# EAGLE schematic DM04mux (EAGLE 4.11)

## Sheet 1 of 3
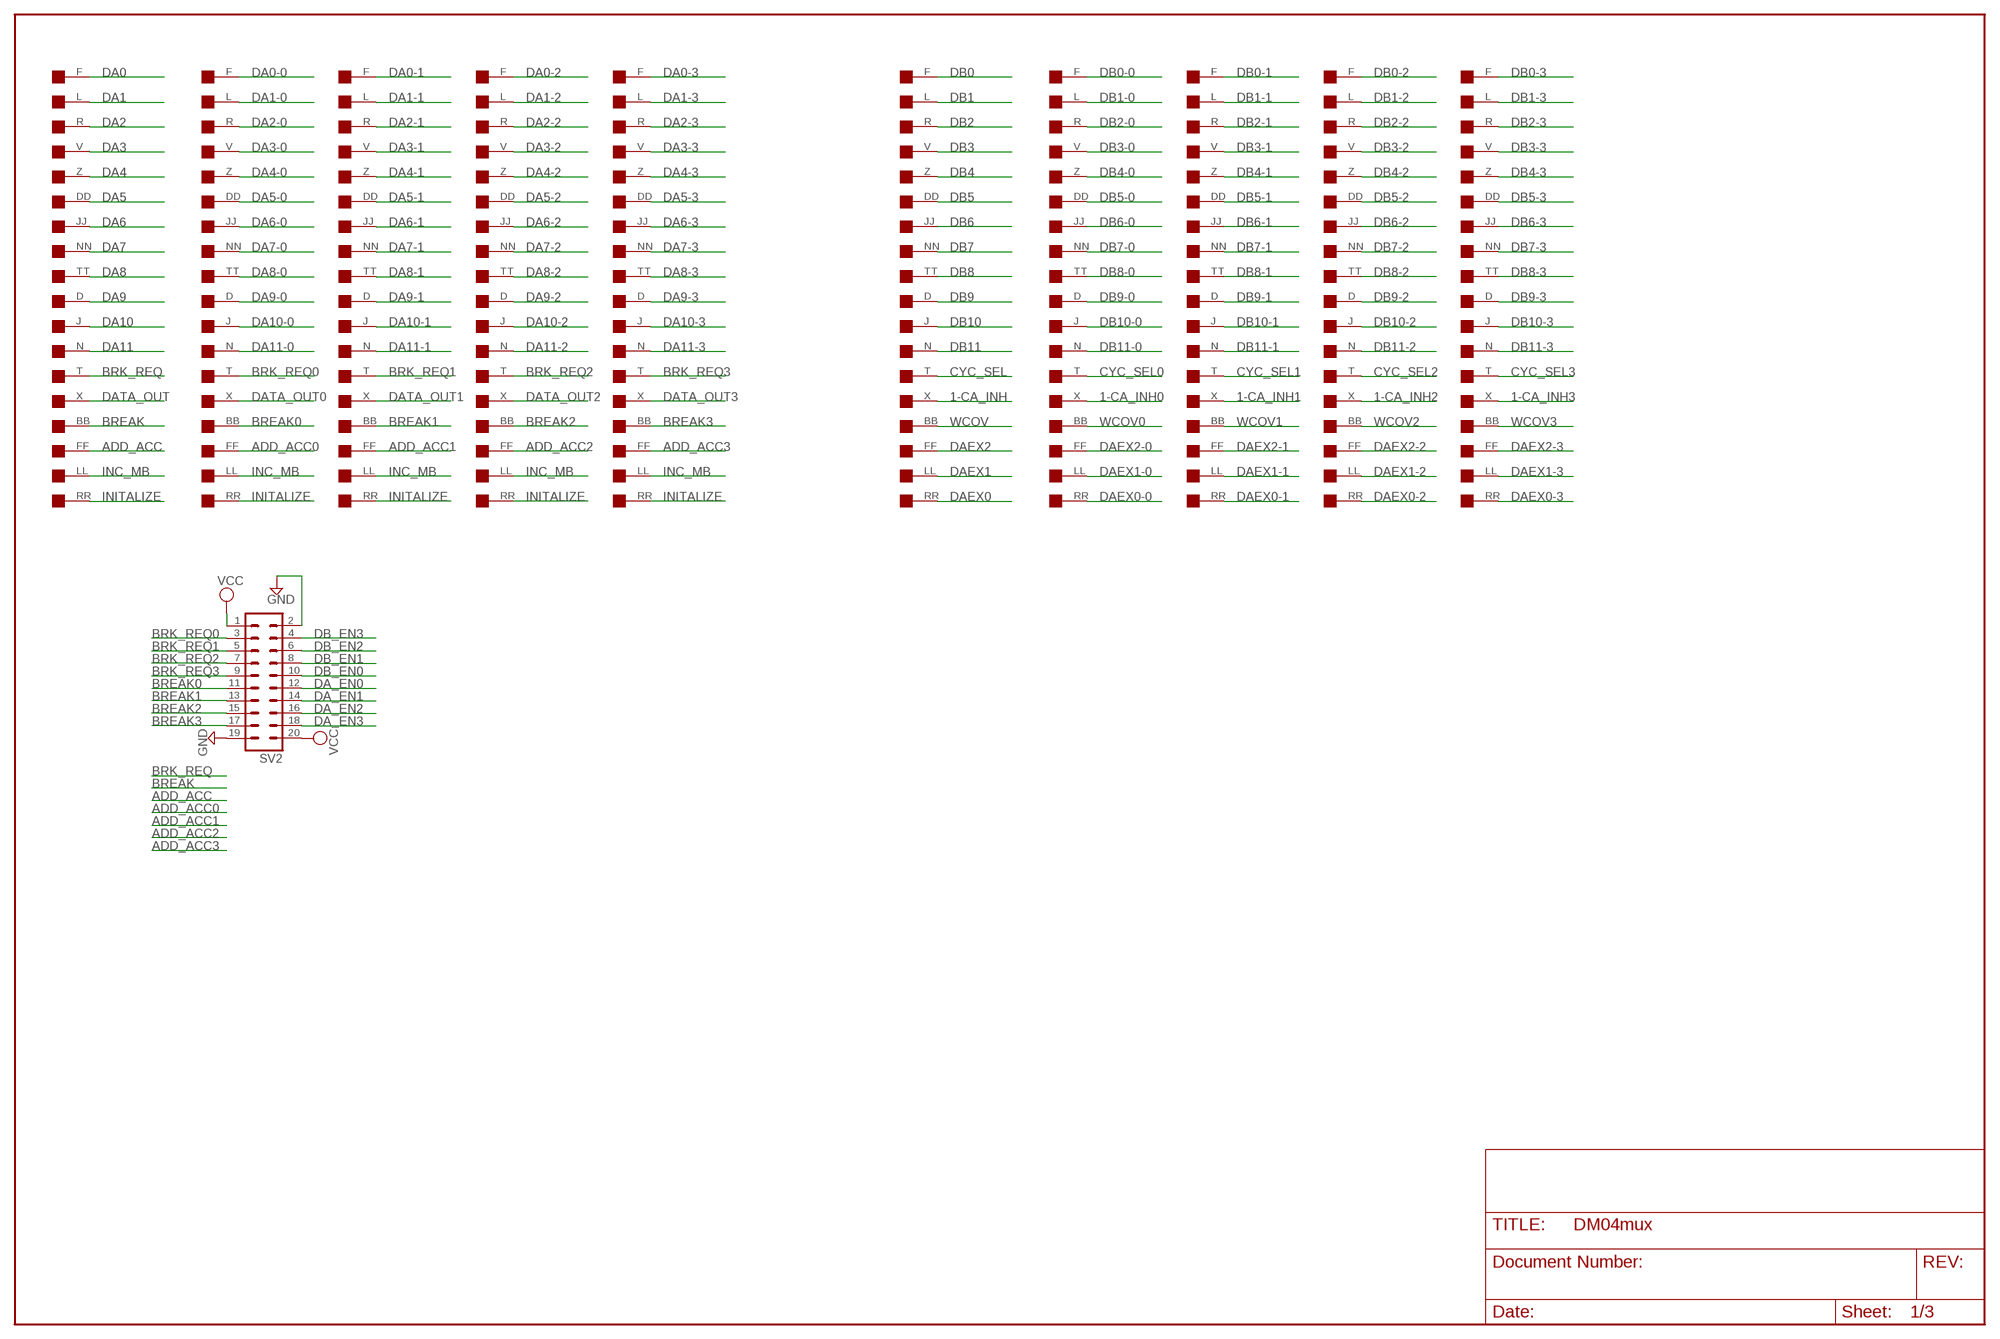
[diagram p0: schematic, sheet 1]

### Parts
SV2  MA10-2  [MA10-2]
U$1  BC08J  [DEC40PINV]
U$2  BC08J  [DEC40PINV]
U$3  BC08J  [DEC40PINV]
U$4  BC08J  [DEC40PINV]
U$5  BC08J  [DEC40PINV]
U$6  BC08J  [DEC40PINV]
U$7  BC08J  [DEC40PINV]
U$8  BC08J  [DEC40PINV]
U$9  BC08J  [DEC40PINV]
U$10  BC08J  [DEC40PINV]

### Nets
1-CA_INH: U$6.X ; also sheet 3
1-CA_INH0: U$7.X ; also sheet 3
1-CA_INH1: U$8.X ; also sheet 3
1-CA_INH2: U$9.X ; also sheet 3
1-CA_INH3: U$10.X ; also sheet 3
ADD_ACC: U$1.FF
ADD_ACC0: U$2.FF
ADD_ACC1: U$3.FF
ADD_ACC2: U$4.FF
ADD_ACC3: U$5.FF
BREAK: U$1.BB
BREAK0: SV2.11 U$2.BB
BREAK1: SV2.13 U$3.BB
BREAK2: SV2.15 U$4.BB
BREAK3: SV2.17 U$5.BB
BRK_REQ: U$1.T
BRK_REQ0: SV2.3 U$2.T
BRK_REQ1: SV2.5 U$3.T
BRK_REQ2: SV2.7 U$4.T
BRK_REQ3: SV2.9 U$5.T
CYC_SEL: U$6.T ; also sheet 2
CYC_SEL0: U$7.T ; also sheet 2
CYC_SEL1: U$8.T ; also sheet 2
CYC_SEL2: U$9.T ; also sheet 2
CYC_SEL3: U$10.T ; also sheet 2
DA0: U$1.F ; also sheet 2
DA0-0: U$2.F ; also sheet 2
DA0-1: U$3.F ; also sheet 2
DA0-2: U$4.F ; also sheet 2
DA0-3: U$5.F ; also sheet 2
DA1: U$1.L ; also sheet 2
DA1-0: U$2.L ; also sheet 2
DA1-1: U$3.L ; also sheet 2
DA1-2: U$4.L ; also sheet 2
DA1-3: U$5.L ; also sheet 2
DA2: U$1.R ; also sheet 2
DA2-0: U$2.R ; also sheet 2
DA2-1: U$3.R ; also sheet 2
DA2-2: U$4.R ; also sheet 2
DA2-3: U$5.R ; also sheet 2
DA3: U$1.V ; also sheet 2
DA3-0: U$2.V ; also sheet 2
DA3-1: U$3.V ; also sheet 2
DA3-2: U$4.V ; also sheet 2
DA3-3: U$5.V ; also sheet 2
DA4: U$1.Z ; also sheet 2
DA4-0: U$2.Z ; also sheet 2
DA4-1: U$3.Z ; also sheet 2
DA4-2: U$4.Z ; also sheet 2
DA4-3: U$5.Z ; also sheet 2
DA5: U$1.DD ; also sheet 2
DA5-0: U$2.DD ; also sheet 2
DA5-1: U$3.DD ; also sheet 2
DA5-2: U$4.DD ; also sheet 2
DA5-3: U$5.DD ; also sheet 2
DA6: U$1.JJ ; also sheet 2
DA6-0: U$2.JJ ; also sheet 2
DA6-1: U$3.JJ ; also sheet 2
DA6-2: U$4.JJ ; also sheet 2
DA6-3: U$5.JJ ; also sheet 2
DA7: U$1.NN ; also sheet 2
DA7-0: U$2.NN ; also sheet 2
DA7-1: U$3.NN ; also sheet 2
DA7-2: U$4.NN ; also sheet 2
DA7-3: U$5.NN ; also sheet 2
DA8: U$1.TT ; also sheet 2
DA8-0: U$2.TT ; also sheet 2
DA8-1: U$3.TT ; also sheet 2
DA8-2: U$4.TT ; also sheet 2
DA8-3: U$5.TT ; also sheet 2
DA9: U$1.D ; also sheet 2
DA9-0: U$2.D ; also sheet 2
DA9-1: U$3.D ; also sheet 2
DA9-2: U$4.D ; also sheet 2
DA9-3: U$5.D ; also sheet 2
DA10: U$1.J ; also sheet 2
DA10-0: U$2.J ; also sheet 2
DA10-1: U$3.J ; also sheet 2
DA10-2: U$4.J ; also sheet 2
DA10-3: U$5.J ; also sheet 2
DA11: U$1.N ; also sheet 2
DA11-0: U$2.N ; also sheet 2
DA11-1: U$3.N ; also sheet 2
DA11-2: U$4.N ; also sheet 2
DA11-3: U$5.N ; also sheet 2
DA_EN0: SV2.12 ; also sheet 2
DA_EN1: SV2.14 ; also sheet 2
DA_EN2: SV2.16 ; also sheet 2
DA_EN3: SV2.18 ; also sheet 2
DAEX0: U$6.RR ; also sheet 2
DAEX0-0: U$7.RR ; also sheet 2
DAEX0-1: U$8.RR ; also sheet 2
DAEX0-2: U$9.RR ; also sheet 2
DAEX0-3: U$10.RR ; also sheet 2
DAEX1: U$6.LL ; also sheet 2
DAEX1-0: U$7.LL ; also sheet 2
DAEX1-1: U$8.LL ; also sheet 2
DAEX1-2: U$9.LL ; also sheet 2
DAEX1-3: U$10.LL ; also sheet 2
DAEX2: U$6.FF ; also sheet 2
DAEX2-0: U$7.FF ; also sheet 2
DAEX2-1: U$8.FF ; also sheet 2
DAEX2-2: U$9.FF ; also sheet 2
DAEX2-3: U$10.FF ; also sheet 2
DATA_OUT: U$1.X ; also sheet 3
DATA_OUT0: U$2.X ; also sheet 3
DATA_OUT1: U$3.X ; also sheet 3
DATA_OUT2: U$4.X ; also sheet 3
DATA_OUT3: U$5.X ; also sheet 3
DB0: U$6.F ; also sheet 3
DB0-0: U$7.F ; also sheet 3
DB0-1: U$8.F ; also sheet 3
DB0-2: U$9.F ; also sheet 3
DB0-3: U$10.F ; also sheet 3
DB1: U$6.L ; also sheet 3
DB1-0: U$7.L ; also sheet 3
DB1-1: U$8.L ; also sheet 3
DB1-2: U$9.L ; also sheet 3
DB1-3: U$10.L ; also sheet 3
DB2: U$6.R ; also sheet 3
DB2-0: U$7.R ; also sheet 3
DB2-1: U$8.R ; also sheet 3
DB2-2: U$9.R ; also sheet 3
DB2-3: U$10.R ; also sheet 3
DB3: U$6.V ; also sheet 3
DB3-0: U$7.V ; also sheet 3
DB3-1: U$8.V ; also sheet 3
DB3-2: U$9.V ; also sheet 3
DB3-3: U$10.V ; also sheet 3
DB4: U$6.Z ; also sheet 3
DB4-0: U$7.Z ; also sheet 3
DB4-1: U$8.Z ; also sheet 3
DB4-2: U$9.Z ; also sheet 3
DB4-3: U$10.Z ; also sheet 3
DB5: U$6.DD ; also sheet 3
DB5-0: U$7.DD ; also sheet 3
DB5-1: U$8.DD ; also sheet 3
DB5-2: U$9.DD ; also sheet 3
DB5-3: U$10.DD ; also sheet 3
DB6: U$6.JJ ; also sheet 3
DB6-0: U$7.JJ ; also sheet 3
DB6-1: U$8.JJ ; also sheet 3
DB6-2: U$9.JJ ; also sheet 3
DB6-3: U$10.JJ ; also sheet 3
DB7: U$6.NN ; also sheet 3
DB7-0: U$7.NN ; also sheet 3
DB7-1: U$8.NN ; also sheet 3
DB7-2: U$9.NN ; also sheet 3
DB7-3: U$10.NN ; also sheet 3
DB8: U$6.TT ; also sheet 3
DB8-0: U$7.TT ; also sheet 3
DB8-1: U$8.TT ; also sheet 3
DB8-2: U$9.TT ; also sheet 3
DB8-3: U$10.TT ; also sheet 3
DB9: U$6.D ; also sheet 3
DB9-0: U$7.D ; also sheet 3
DB9-1: U$8.D ; also sheet 3
DB9-2: U$9.D ; also sheet 3
DB9-3: U$10.D ; also sheet 3
DB10: U$6.J ; also sheet 3
DB10-0: U$7.J ; also sheet 3
DB10-1: U$8.J ; also sheet 3
DB10-2: U$9.J ; also sheet 3
DB10-3: U$10.J ; also sheet 3
DB11: U$6.N ; also sheet 3
DB11-0: U$7.N ; also sheet 3
DB11-1: U$8.N ; also sheet 3
DB11-2: U$9.N ; also sheet 3
DB11-3: U$10.N ; also sheet 3
DB_EN0: SV2.10 ; also sheet 3
DB_EN1: SV2.8 ; also sheet 3
DB_EN2: SV2.6 ; also sheet 3
DB_EN3: SV2.4 ; also sheet 3
GND: SV2.2 SV2.19 ; also sheet 3
INC_MB: U$1.LL U$2.LL U$3.LL U$4.LL U$5.LL
INITALIZE: U$1.RR U$2.RR U$3.RR U$4.RR U$5.RR
VCC: SV2.1 SV2.20 ; also sheet 2,3
WCOV: U$6.BB
WCOV0: U$7.BB
WCOV1: U$8.BB
WCOV2: U$9.BB
WCOV3: U$10.BB

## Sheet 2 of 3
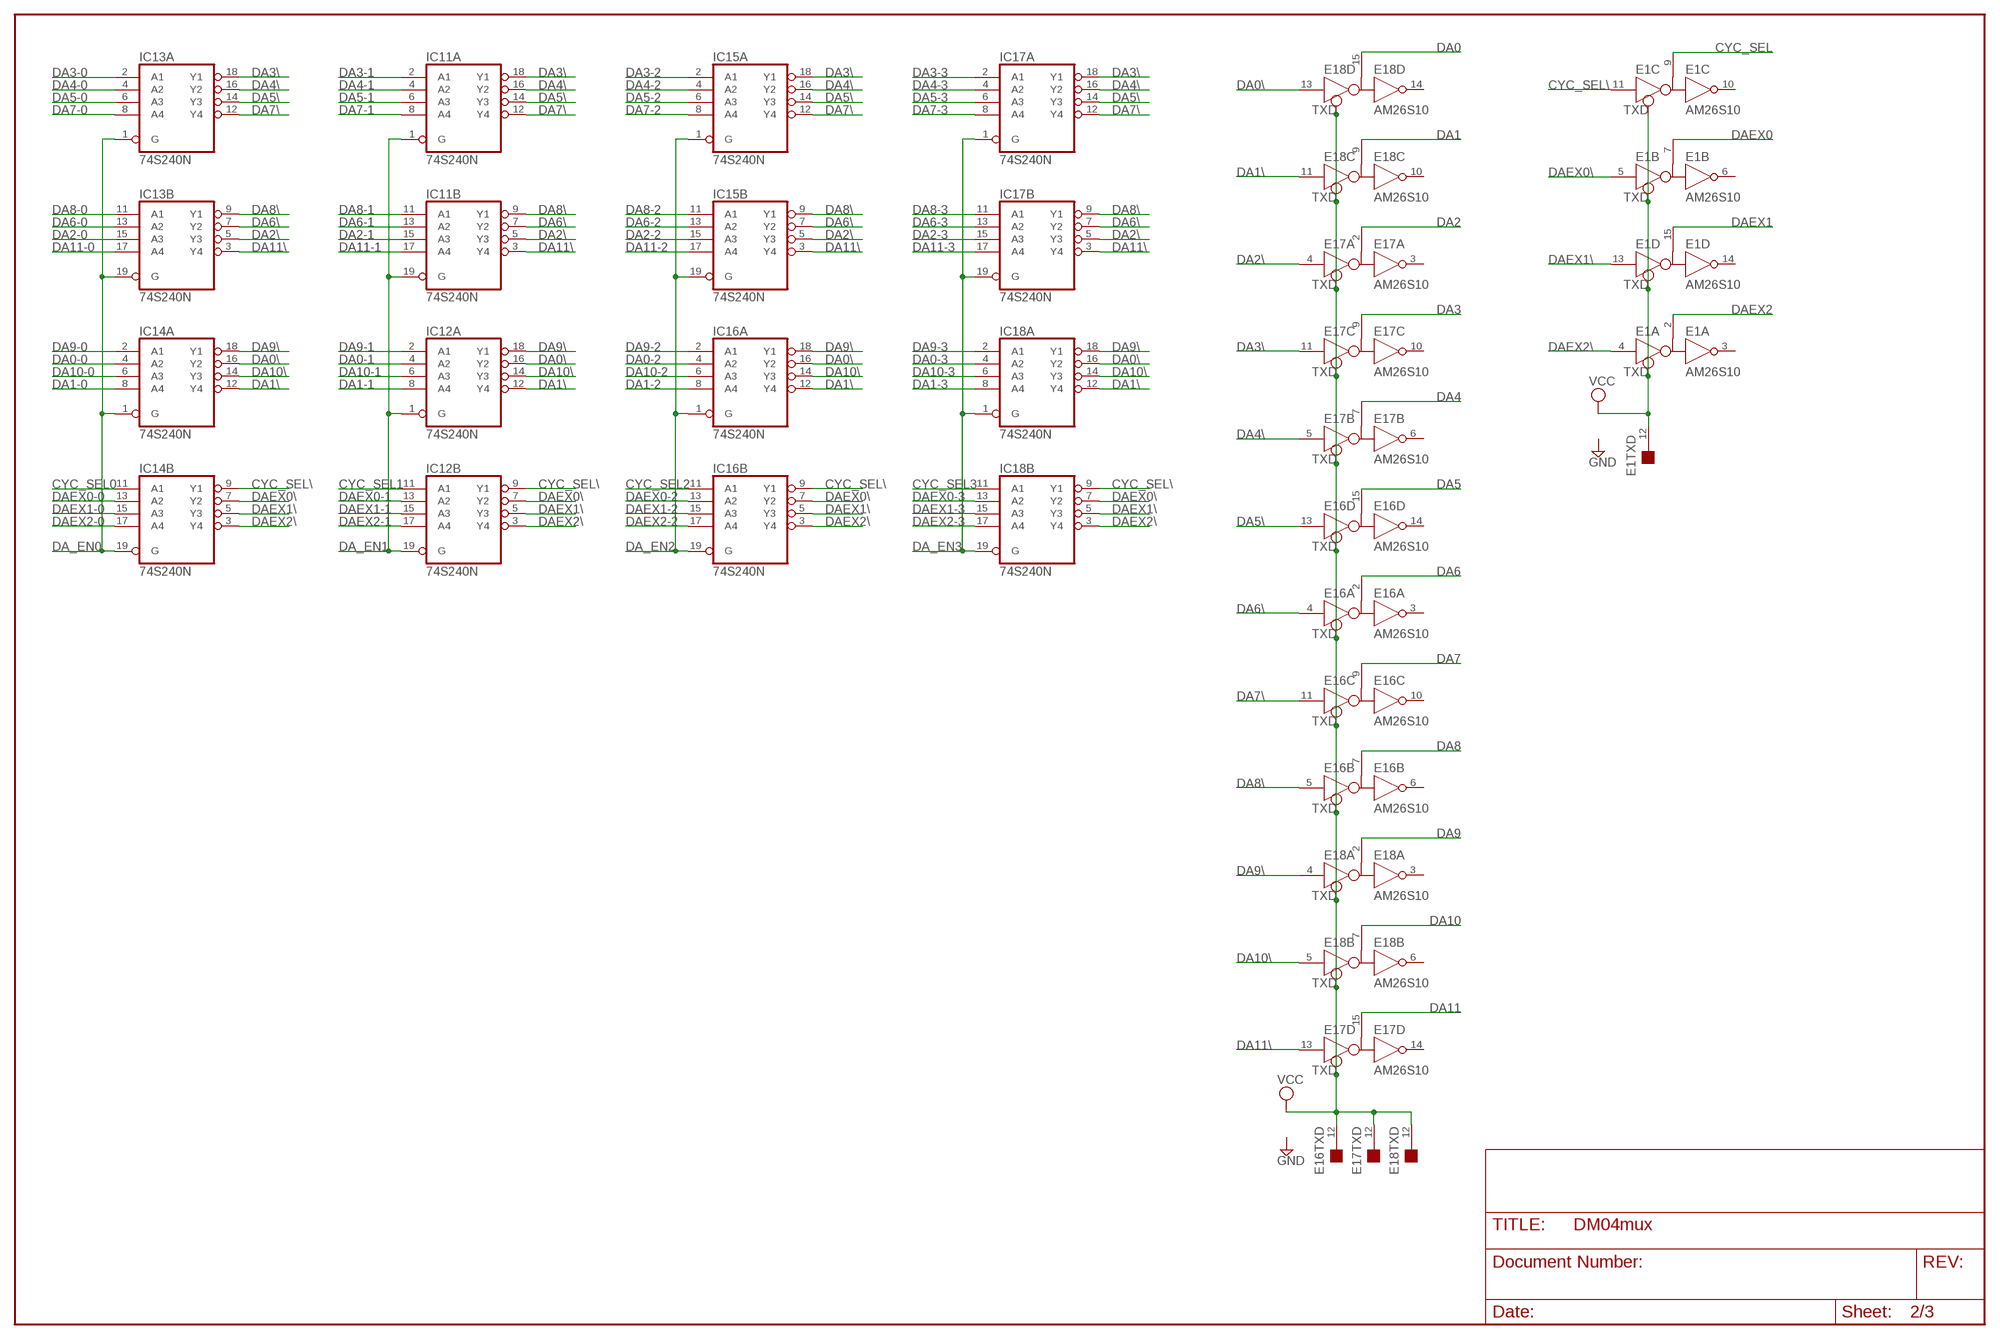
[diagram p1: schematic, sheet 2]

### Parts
E1  AM26S10  [DIL16]
E16  AM26S10  [DIL16]
E17  AM26S10  [DIL16]
E18  AM26S10  [DIL16]
IC11  74S240N  [DIL20]
IC12  74S240N  [DIL20]
IC13  74S240N  [DIL20]
IC14  74S240N  [DIL20]
IC15  74S240N  [DIL20]
IC16  74S240N  [DIL20]
IC17  74S240N  [DIL20]
IC18  74S240N  [DIL20]

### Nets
CYC_SEL: E1.9(C:B) ; also sheet 1
CYC_SEL0: IC14.11(B:A1) ; also sheet 1
CYC_SEL1: IC12.11(B:A1) ; also sheet 1
CYC_SEL2: IC16.11(B:A1) ; also sheet 1
CYC_SEL3: IC18.11(B:A1) ; also sheet 1
CYC_SEL\: E1.11(C:D) IC12.9(B:Y1) IC14.9(B:Y1) IC16.9(B:Y1) IC18.9(B:Y1)
DA0: E18.15(D:B) ; also sheet 1
DA0-0: IC14.4(A:A2) ; also sheet 1
DA0-1: IC12.4(A:A2) ; also sheet 1
DA0-2: IC16.4(A:A2) ; also sheet 1
DA0-3: IC18.4(A:A2) ; also sheet 1
DA0\: E18.13(D:D) IC12.16(A:Y2) IC14.16(A:Y2) IC16.16(A:Y2) IC18.16(A:Y2)
DA1: E18.9(C:B) ; also sheet 1
DA1-0: IC14.8(A:A4) ; also sheet 1
DA1-1: IC12.8(A:A4) ; also sheet 1
DA1-2: IC16.8(A:A4) ; also sheet 1
DA1-3: IC18.8(A:A4) ; also sheet 1
DA1\: E18.11(C:D) IC12.12(A:Y4) IC14.12(A:Y4) IC16.12(A:Y4) IC18.12(A:Y4)
DA2: E17.2(A:B) ; also sheet 1
DA2-0: IC13.15(B:A3) ; also sheet 1
DA2-1: IC11.15(B:A3) ; also sheet 1
DA2-2: IC15.15(B:A3) ; also sheet 1
DA2-3: IC17.15(B:A3) ; also sheet 1
DA2\: E17.4(A:D) IC11.5(B:Y3) IC13.5(B:Y3) IC15.5(B:Y3) IC17.5(B:Y3)
DA3: E17.9(C:B) ; also sheet 1
DA3-0: IC13.2(A:A1) ; also sheet 1
DA3-1: IC11.2(A:A1) ; also sheet 1
DA3-2: IC15.2(A:A1) ; also sheet 1
DA3-3: IC17.2(A:A1) ; also sheet 1
DA3\: E17.11(C:D) IC11.18(A:Y1) IC13.18(A:Y1) IC15.18(A:Y1) IC17.18(A:Y1)
DA4: E17.7(B:B) ; also sheet 1
DA4-0: IC13.4(A:A2) ; also sheet 1
DA4-1: IC11.4(A:A2) ; also sheet 1
DA4-2: IC15.4(A:A2) ; also sheet 1
DA4-3: IC17.4(A:A2) ; also sheet 1
DA4\: E17.5(B:D) IC11.16(A:Y2) IC13.16(A:Y2) IC15.16(A:Y2) IC17.16(A:Y2)
DA5: E16.15(D:B) ; also sheet 1
DA5-0: IC13.6(A:A3) ; also sheet 1
DA5-1: IC11.6(A:A3) ; also sheet 1
DA5-2: IC15.6(A:A3) ; also sheet 1
DA5-3: IC17.6(A:A3) ; also sheet 1
DA5\: E16.13(D:D) IC11.14(A:Y3) IC13.14(A:Y3) IC15.14(A:Y3) IC17.14(A:Y3)
DA6: E16.2(A:B) ; also sheet 1
DA6-0: IC13.13(B:A2) ; also sheet 1
DA6-1: IC11.13(B:A2) ; also sheet 1
DA6-2: IC15.13(B:A2) ; also sheet 1
DA6-3: IC17.13(B:A2) ; also sheet 1
DA6\: E16.4(A:D) IC11.7(B:Y2) IC13.7(B:Y2) IC15.7(B:Y2) IC17.7(B:Y2)
DA7: E16.9(C:B) ; also sheet 1
DA7-0: IC13.8(A:A4) ; also sheet 1
DA7-1: IC11.8(A:A4) ; also sheet 1
DA7-2: IC15.8(A:A4) ; also sheet 1
DA7-3: IC17.8(A:A4) ; also sheet 1
DA7\: E16.11(C:D) IC11.12(A:Y4) IC13.12(A:Y4) IC15.12(A:Y4) IC17.12(A:Y4)
DA8: E16.7(B:B) ; also sheet 1
DA8-0: IC13.11(B:A1) ; also sheet 1
DA8-1: IC11.11(B:A1) ; also sheet 1
DA8-2: IC15.11(B:A1) ; also sheet 1
DA8-3: IC17.11(B:A1) ; also sheet 1
DA8\: E16.5(B:D) IC11.9(B:Y1) IC13.9(B:Y1) IC15.9(B:Y1) IC17.9(B:Y1)
DA9: E18.2(A:B) ; also sheet 1
DA9-0: IC14.2(A:A1) ; also sheet 1
DA9-1: IC12.2(A:A1) ; also sheet 1
DA9-2: IC16.2(A:A1) ; also sheet 1
DA9-3: IC18.2(A:A1) ; also sheet 1
DA9\: E18.4(A:D) IC12.18(A:Y1) IC14.18(A:Y1) IC16.18(A:Y1) IC18.18(A:Y1)
DA10: E18.7(B:B) ; also sheet 1
DA10-0: IC14.6(A:A3) ; also sheet 1
DA10-1: IC12.6(A:A3) ; also sheet 1
DA10-2: IC16.6(A:A3) ; also sheet 1
DA10-3: IC18.6(A:A3) ; also sheet 1
DA10\: E18.5(B:D) IC12.14(A:Y3) IC14.14(A:Y3) IC16.14(A:Y3) IC18.14(A:Y3)
DA11: E17.15(D:B) ; also sheet 1
DA11-0: IC13.17(B:A4) ; also sheet 1
DA11-1: IC11.17(B:A4) ; also sheet 1
DA11-2: IC15.17(B:A4) ; also sheet 1
DA11-3: IC17.17(B:A4) ; also sheet 1
DA11\: E17.13(D:D) IC11.3(B:Y4) IC13.3(B:Y4) IC15.3(B:Y4) IC17.3(B:Y4)
DA_EN0: IC13.1(A:G) IC13.19(B:G) IC14.1(A:G) IC14.19(B:G) ; also sheet 1
DA_EN1: IC11.1(A:G) IC11.19(B:G) IC12.1(A:G) IC12.19(B:G) ; also sheet 1
DA_EN2: IC15.1(A:G) IC15.19(B:G) IC16.1(A:G) IC16.19(B:G) ; also sheet 1
DA_EN3: IC17.1(A:G) IC17.19(B:G) IC18.1(A:G) IC18.19(B:G) ; also sheet 1
DAEX0: E1.7(B:B) ; also sheet 1
DAEX0-0: IC14.13(B:A2) ; also sheet 1
DAEX0-1: IC12.13(B:A2) ; also sheet 1
DAEX0-2: IC16.13(B:A2) ; also sheet 1
DAEX0-3: IC18.13(B:A2) ; also sheet 1
DAEX0\: E1.5(B:D) IC12.7(B:Y2) IC14.7(B:Y2) IC16.7(B:Y2) IC18.7(B:Y2)
DAEX1: E1.15(D:B) ; also sheet 1
DAEX1-0: IC14.15(B:A3) ; also sheet 1
DAEX1-1: IC12.15(B:A3) ; also sheet 1
DAEX1-2: IC16.15(B:A3) ; also sheet 1
DAEX1-3: IC18.15(B:A3) ; also sheet 1
DAEX1\: E1.13(D:D) IC12.5(B:Y3) IC14.5(B:Y3) IC16.5(B:Y3) IC18.5(B:Y3)
DAEX2: E1.2(A:B) ; also sheet 1
DAEX2-0: IC14.17(B:A4) ; also sheet 1
DAEX2-1: IC12.17(B:A4) ; also sheet 1
DAEX2-2: IC16.17(B:A4) ; also sheet 1
DAEX2-3: IC18.17(B:A4) ; also sheet 1
DAEX2\: E1.4(A:D) IC12.3(B:Y4) IC14.3(B:Y4) IC16.3(B:Y4) IC18.3(B:Y4)
VCC: E1.12(TXD:TXD) E16.12(TXD:TXD) E17.12(TXD:TXD) E18.12(TXD:TXD) ; also sheet 1,3
Unconnected: E1.3(A:R) E1.6(B:R) E1.10(C:R) E1.14(D:R) E16.3(A:R) E16.6(B:R) E16.10(C:R) E16.14(D:R) E17.3(A:R) E17.6(B:R) E17.10(C:R) E17.14(D:R) E18.3(A:R) E18.6(B:R) E18.10(C:R) E18.14(D:R)

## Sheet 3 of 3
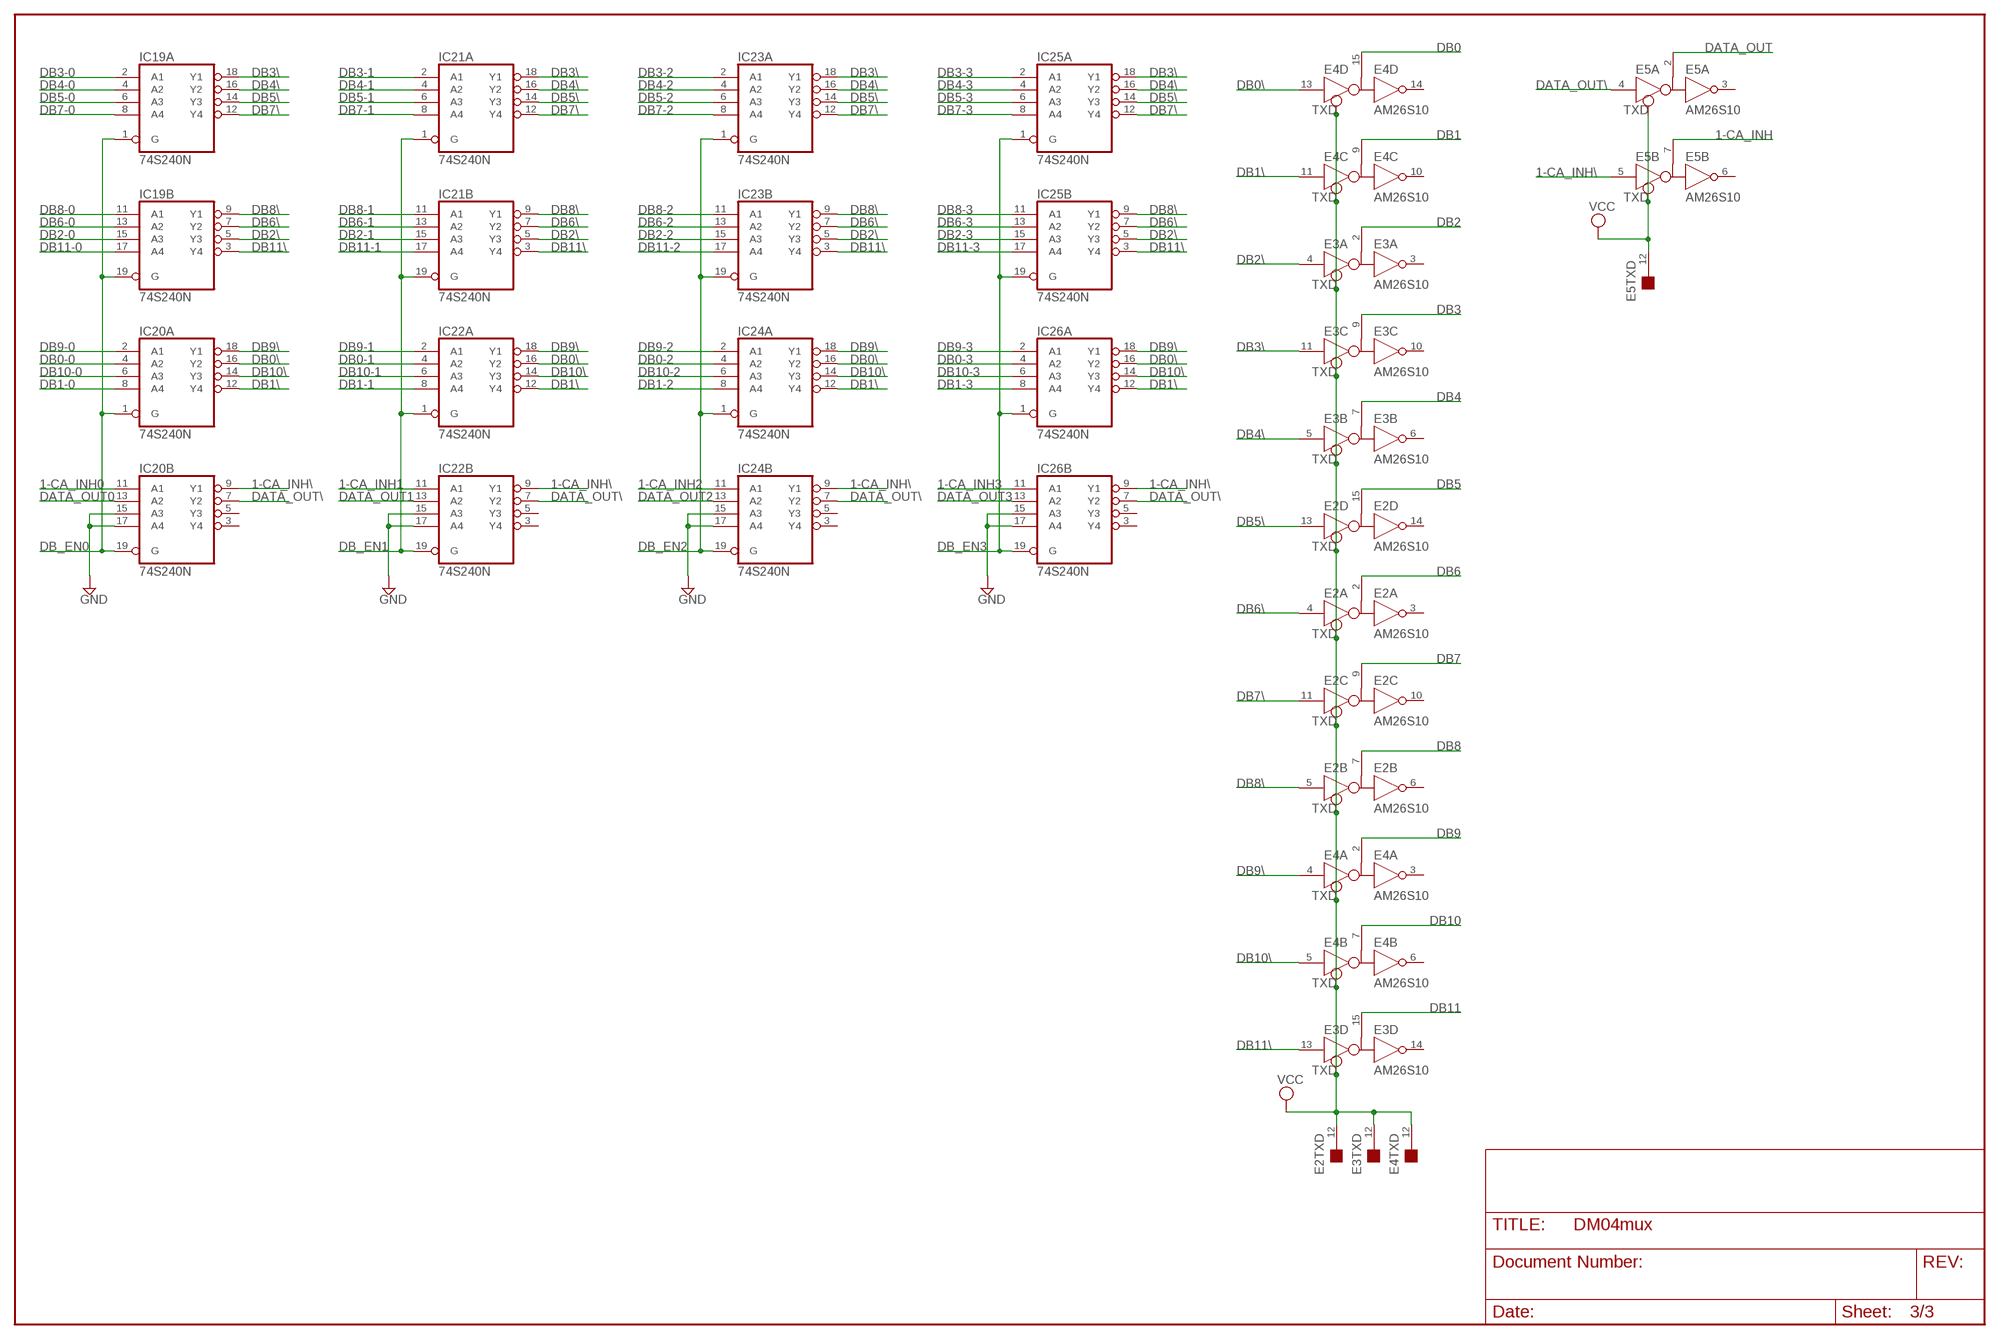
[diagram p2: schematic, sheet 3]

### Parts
E2  AM26S10  [DIL16]
E3  AM26S10  [DIL16]
E4  AM26S10  [DIL16]
E5  AM26S10  [DIL16]
IC19  74S240N  [DIL20]
IC20  74S240N  [DIL20]
IC21  74S240N  [DIL20]
IC22  74S240N  [DIL20]
IC23  74S240N  [DIL20]
IC24  74S240N  [DIL20]
IC25  74S240N  [DIL20]
IC26  74S240N  [DIL20]

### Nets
1-CA_INH: E5.7(B:B) ; also sheet 1
1-CA_INH0: IC20.11(B:A1) ; also sheet 1
1-CA_INH1: IC22.11(B:A1) ; also sheet 1
1-CA_INH2: IC24.11(B:A1) ; also sheet 1
1-CA_INH3: IC26.11(B:A1) ; also sheet 1
1-CA_INH\: E5.5(B:D) IC20.9(B:Y1) IC22.9(B:Y1) IC24.9(B:Y1) IC26.9(B:Y1)
DATA_OUT: E5.2(A:B) ; also sheet 1
DATA_OUT0: IC20.13(B:A2) ; also sheet 1
DATA_OUT1: IC22.13(B:A2) ; also sheet 1
DATA_OUT2: IC24.13(B:A2) ; also sheet 1
DATA_OUT3: IC26.13(B:A2) ; also sheet 1
DATA_OUT\: E5.4(A:D) IC20.7(B:Y2) IC22.7(B:Y2) IC24.7(B:Y2) IC26.7(B:Y2)
DB0: E4.15(D:B) ; also sheet 1
DB0-0: IC20.4(A:A2) ; also sheet 1
DB0-1: IC22.4(A:A2) ; also sheet 1
DB0-2: IC24.4(A:A2) ; also sheet 1
DB0-3: IC26.4(A:A2) ; also sheet 1
DB0\: E4.13(D:D) IC20.16(A:Y2) IC22.16(A:Y2) IC24.16(A:Y2) IC26.16(A:Y2)
DB1: E4.9(C:B) ; also sheet 1
DB1-0: IC20.8(A:A4) ; also sheet 1
DB1-1: IC22.8(A:A4) ; also sheet 1
DB1-2: IC24.8(A:A4) ; also sheet 1
DB1-3: IC26.8(A:A4) ; also sheet 1
DB1\: E4.11(C:D) IC20.12(A:Y4) IC22.12(A:Y4) IC24.12(A:Y4) IC26.12(A:Y4)
DB2: E3.2(A:B) ; also sheet 1
DB2-0: IC19.15(B:A3) ; also sheet 1
DB2-1: IC21.15(B:A3) ; also sheet 1
DB2-2: IC23.15(B:A3) ; also sheet 1
DB2-3: IC25.15(B:A3) ; also sheet 1
DB2\: E3.4(A:D) IC19.5(B:Y3) IC21.5(B:Y3) IC23.5(B:Y3) IC25.5(B:Y3)
DB3: E3.9(C:B) ; also sheet 1
DB3-0: IC19.2(A:A1) ; also sheet 1
DB3-1: IC21.2(A:A1) ; also sheet 1
DB3-2: IC23.2(A:A1) ; also sheet 1
DB3-3: IC25.2(A:A1) ; also sheet 1
DB3\: E3.11(C:D) IC19.18(A:Y1) IC21.18(A:Y1) IC23.18(A:Y1) IC25.18(A:Y1)
DB4: E3.7(B:B) ; also sheet 1
DB4-0: IC19.4(A:A2) ; also sheet 1
DB4-1: IC21.4(A:A2) ; also sheet 1
DB4-2: IC23.4(A:A2) ; also sheet 1
DB4-3: IC25.4(A:A2) ; also sheet 1
DB4\: E3.5(B:D) IC19.16(A:Y2) IC21.16(A:Y2) IC23.16(A:Y2) IC25.16(A:Y2)
DB5: E2.15(D:B) ; also sheet 1
DB5-0: IC19.6(A:A3) ; also sheet 1
DB5-1: IC21.6(A:A3) ; also sheet 1
DB5-2: IC23.6(A:A3) ; also sheet 1
DB5-3: IC25.6(A:A3) ; also sheet 1
DB5\: E2.13(D:D) IC19.14(A:Y3) IC21.14(A:Y3) IC23.14(A:Y3) IC25.14(A:Y3)
DB6: E2.2(A:B) ; also sheet 1
DB6-0: IC19.13(B:A2) ; also sheet 1
DB6-1: IC21.13(B:A2) ; also sheet 1
DB6-2: IC23.13(B:A2) ; also sheet 1
DB6-3: IC25.13(B:A2) ; also sheet 1
DB6\: E2.4(A:D) IC19.7(B:Y2) IC21.7(B:Y2) IC23.7(B:Y2) IC25.7(B:Y2)
DB7: E2.9(C:B) ; also sheet 1
DB7-0: IC19.8(A:A4) ; also sheet 1
DB7-1: IC21.8(A:A4) ; also sheet 1
DB7-2: IC23.8(A:A4) ; also sheet 1
DB7-3: IC25.8(A:A4) ; also sheet 1
DB7\: E2.11(C:D) IC19.12(A:Y4) IC21.12(A:Y4) IC23.12(A:Y4) IC25.12(A:Y4)
DB8: E2.7(B:B) ; also sheet 1
DB8-0: IC19.11(B:A1) ; also sheet 1
DB8-1: IC21.11(B:A1) ; also sheet 1
DB8-2: IC23.11(B:A1) ; also sheet 1
DB8-3: IC25.11(B:A1) ; also sheet 1
DB8\: E2.5(B:D) IC19.9(B:Y1) IC21.9(B:Y1) IC23.9(B:Y1) IC25.9(B:Y1)
DB9: E4.2(A:B) ; also sheet 1
DB9-0: IC20.2(A:A1) ; also sheet 1
DB9-1: IC22.2(A:A1) ; also sheet 1
DB9-2: IC24.2(A:A1) ; also sheet 1
DB9-3: IC26.2(A:A1) ; also sheet 1
DB9\: E4.4(A:D) IC20.18(A:Y1) IC22.18(A:Y1) IC24.18(A:Y1) IC26.18(A:Y1)
DB10: E4.7(B:B) ; also sheet 1
DB10-0: IC20.6(A:A3) ; also sheet 1
DB10-1: IC22.6(A:A3) ; also sheet 1
DB10-2: IC24.6(A:A3) ; also sheet 1
DB10-3: IC26.6(A:A3) ; also sheet 1
DB10\: E4.5(B:D) IC20.14(A:Y3) IC22.14(A:Y3) IC24.14(A:Y3) IC26.14(A:Y3)
DB11: E3.15(D:B) ; also sheet 1
DB11-0: IC19.17(B:A4) ; also sheet 1
DB11-1: IC21.17(B:A4) ; also sheet 1
DB11-2: IC23.17(B:A4) ; also sheet 1
DB11-3: IC25.17(B:A4) ; also sheet 1
DB11\: E3.13(D:D) IC19.3(B:Y4) IC21.3(B:Y4) IC23.3(B:Y4) IC25.3(B:Y4)
DB_EN0: IC19.1(A:G) IC19.19(B:G) IC20.1(A:G) IC20.19(B:G) ; also sheet 1
DB_EN1: IC21.1(A:G) IC21.19(B:G) IC22.1(A:G) IC22.19(B:G) ; also sheet 1
DB_EN2: IC23.1(A:G) IC23.19(B:G) IC24.1(A:G) IC24.19(B:G) ; also sheet 1
DB_EN3: IC25.1(A:G) IC25.19(B:G) IC26.1(A:G) IC26.19(B:G) ; also sheet 1
GND: IC20.15(B:A3) IC20.17(B:A4) IC22.15(B:A3) IC22.17(B:A4) IC24.15(B:A3) IC24.17(B:A4) IC26.15(B:A3) IC26.17(B:A4) ; also sheet 1
VCC: E2.12(TXD:TXD) E3.12(TXD:TXD) E4.12(TXD:TXD) E5.12(TXD:TXD) ; also sheet 1,2
Unconnected: E2.3(A:R) E2.6(B:R) E2.10(C:R) E2.14(D:R) E3.3(A:R) E3.6(B:R) E3.10(C:R) E3.14(D:R) E4.3(A:R) E4.6(B:R) E4.10(C:R) E4.14(D:R) E5.3(A:R) E5.6(B:R) E5.9(C:B) E5.10(C:R) E5.11(C:D) E5.13(D:D) E5.14(D:R) E5.15(D:B) IC20.3(B:Y4) IC20.5(B:Y3) IC22.3(B:Y4) IC22.5(B:Y3) IC24.3(B:Y4) IC24.5(B:Y3) IC26.3(B:Y4) IC26.5(B:Y3)

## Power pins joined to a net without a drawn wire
GND: E1.1(GND:GND) E1.8(PWR:GND) E2.1(GND:GND) E2.8(PWR:GND) E3.1(GND:GND) E3.8(PWR:GND) E4.1(GND:GND) E4.8(PWR:GND) E5.1(GND:GND) E5.8(PWR:GND) E16.1(GND:GND) E16.8(PWR:GND) E17.1(GND:GND) E17.8(PWR:GND) E18.1(GND:GND) E18.8(PWR:GND) IC11.10(P:GND) IC12.10(P:GND) IC13.10(P:GND) IC14.10(P:GND) IC15.10(P:GND) IC16.10(P:GND) IC17.10(P:GND) IC18.10(P:GND) IC19.10(P:GND) IC20.10(P:GND) IC21.10(P:GND) IC22.10(P:GND) IC23.10(P:GND) IC24.10(P:GND) IC25.10(P:GND) IC26.10(P:GND) U$1.A U$1.AA U$1.B U$1.C U$1.CC U$1.E U$1.EE U$1.H U$1.HH U$1.K U$1.KK U$1.M U$1.MM U$1.P U$1.PP U$1.S U$1.SS U$1.U U$1.UU U$1.VV U$1.W U$1.Y U$2.A U$2.AA U$2.B U$2.C U$2.CC U$2.E U$2.EE U$2.H U$2.HH U$2.K U$2.KK U$2.M U$2.MM U$2.P U$2.PP U$2.S U$2.SS U$2.U U$2.UU U$2.VV U$2.W U$2.Y U$3.A U$3.AA U$3.B U$3.C U$3.CC U$3.E U$3.EE U$3.H U$3.HH U$3.K U$3.KK U$3.M U$3.MM U$3.P U$3.PP U$3.S U$3.SS U$3.U U$3.UU U$3.VV U$3.W U$3.Y U$4.A U$4.AA U$4.B U$4.C U$4.CC U$4.E U$4.EE U$4.H U$4.HH U$4.K U$4.KK U$4.M U$4.MM U$4.P U$4.PP U$4.S U$4.SS U$4.U U$4.UU U$4.VV U$4.W U$4.Y U$5.A U$5.AA U$5.B U$5.C U$5.CC U$5.E U$5.EE U$5.H U$5.HH U$5.K U$5.KK U$5.M U$5.MM U$5.P U$5.PP U$5.S U$5.SS U$5.U U$5.UU U$5.VV U$5.W U$5.Y U$6.A U$6.AA U$6.B U$6.C U$6.CC U$6.E U$6.EE U$6.H U$6.HH U$6.K U$6.KK U$6.M U$6.MM U$6.P U$6.PP U$6.S U$6.SS U$6.U U$6.UU U$6.VV U$6.W U$6.Y U$7.A U$7.AA U$7.B U$7.C U$7.CC U$7.E U$7.EE U$7.H U$7.HH U$7.K U$7.KK U$7.M U$7.MM U$7.P U$7.PP U$7.S U$7.SS U$7.U U$7.UU U$7.VV U$7.W U$7.Y U$8.A U$8.AA U$8.B U$8.C U$8.CC U$8.E U$8.EE U$8.H U$8.HH U$8.K U$8.KK U$8.M U$8.MM U$8.P U$8.PP U$8.S U$8.SS U$8.U U$8.UU U$8.VV U$8.W U$8.Y U$9.A U$9.AA U$9.B U$9.C U$9.CC U$9.E U$9.EE U$9.H U$9.HH U$9.K U$9.KK U$9.M U$9.MM U$9.P U$9.PP U$9.S U$9.SS U$9.U U$9.UU U$9.VV U$9.W U$9.Y U$10.A U$10.AA U$10.B U$10.C U$10.CC U$10.E U$10.EE U$10.H U$10.HH U$10.K U$10.KK U$10.M U$10.MM U$10.P U$10.PP U$10.S U$10.SS U$10.U U$10.UU U$10.VV U$10.W U$10.Y
VCC: E1.16(PWR:VCC) E2.16(PWR:VCC) E3.16(PWR:VCC) E4.16(PWR:VCC) E5.16(PWR:VCC) E16.16(PWR:VCC) E17.16(PWR:VCC) E18.16(PWR:VCC) IC11.20(P:VCC) IC12.20(P:VCC) IC13.20(P:VCC) IC14.20(P:VCC) IC15.20(P:VCC) IC16.20(P:VCC) IC17.20(P:VCC) IC18.20(P:VCC) IC19.20(P:VCC) IC20.20(P:VCC) IC21.20(P:VCC) IC22.20(P:VCC) IC23.20(P:VCC) IC24.20(P:VCC) IC25.20(P:VCC) IC26.20(P:VCC)

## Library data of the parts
E1-E5 E16-E18 = dec-con:AM26S10: Bus Transceiver
IC11-IC26 = 74xx-jameco:74*240: Octal BUFFER and LINE DRIVER, 3-state
SV2 = con-lstb:MA10-2: PIN HEADER
U$1-U$10 = dec-con:BC08J: BC08J compatible bus connector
